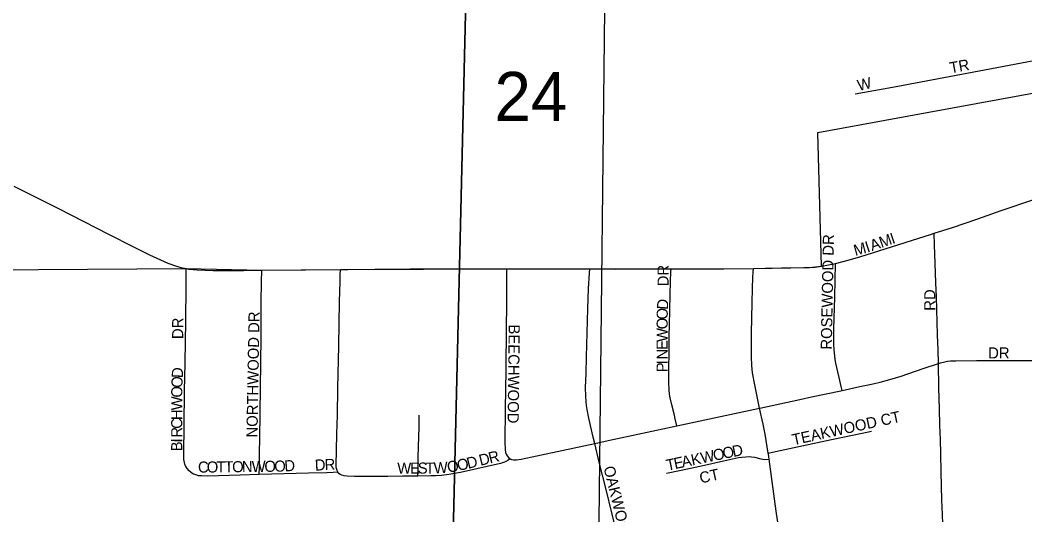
# Model space of a CAD drawing. Extents: x 0 to 34, y 0 to 22.
# Drawn here: x 4.7754 to 5.2041, y 18.5597 to 18.7709 of the extents above; entities that cross this region are included whole.
import ezdxf

# ---------------------------------------------------------------- set-up
doc = ezdxf.new("R2010")
doc.units = 0
for name, color, linetype in [('GM_X_City_Street', 7, 'Continuous'), ('GM_X_City_Street_Text', 7, 'Continuous'), ('GM_X_Corporation', 7, 'Continuous'), ('GM_X_County_Road', 7, 'Continuous'), ('GM_X_Section', 7, 'Continuous'), ('GM_X_Section_Text', 7, 'Continuous')]:
    doc.layers.add(name, color=color, linetype=linetype)

msp = doc.modelspace()

# ---------------------------------------------------------------- linework, layer by layer
at = {"layer": 'GM_X_City_Street'}
for points in [[(5.13165, 18.73941), (5.14761, 18.74238), (5.162, 18.74505), (5.1868, 18.74968), (5.20785, 18.75366), (5.22221, 18.75626), (5.22954, 18.75761), (5.2375, 18.75916), (5.2537, 18.76214), (5.28766, 18.76837)], [(5.16537, 18.67995), (5.17314, 18.68248), (5.18403, 18.68616), (5.19401, 18.68965), (5.2074, 18.69418)], [(5.12335, 18.66709), (5.12598, 18.66772), (5.12871, 18.66843), (5.13406, 18.66997), (5.14176, 18.67241), (5.16428, 18.67959), (5.16537, 18.67995)], [(5.16723, 18.62437), (5.16705, 18.63018), (5.16685, 18.63662), (5.16633, 18.65278), (5.16612, 18.65875), (5.16567, 18.67113), (5.16554, 18.67485), (5.16537, 18.67995)], [(4.84831, 18.57794), (4.84753, 18.5786), (4.84667, 18.5796), (4.84599, 18.58074), (4.84571, 18.58134), (4.84551, 18.58207), (4.84529, 18.58339), (4.84522, 18.58586), (4.84539, 18.59794), (4.84562, 18.61255), (4.84579, 18.62468), (4.84607, 18.64242), (4.84631, 18.65731), (4.84625, 18.66485)], [(4.87744, 18.57712), (4.87749, 18.57996), (4.8776, 18.58628), (4.8777, 18.59253), (4.87827, 18.63547), (4.87831, 18.64293), (4.87834, 18.65073), (4.87847, 18.6591), (4.87854, 18.66417)], [(4.91092, 18.57814), (4.91066, 18.57863), (4.9105, 18.57908), (4.91038, 18.57961), (4.91033, 18.58027), (4.91027, 18.58093), (4.91042, 18.58737), (4.9106, 18.5944), (4.91077, 18.60238), (4.91097, 18.61386), (4.9114, 18.63187), (4.91175, 18.65081), (4.91197, 18.65926), (4.91204, 18.6621), (4.91211, 18.66452)], [(4.98299, 18.66481), (4.98296, 18.6615), (4.98293, 18.65871), (4.98292, 18.65561), (4.98289, 18.64874), (4.98278, 18.64029), (4.98266, 18.62143), (4.98241, 18.60496), (4.98224, 18.59078), (4.98236, 18.58761), (4.98254, 18.58645), (4.9828, 18.58563), (4.98319, 18.58489), (4.98372, 18.58426), (4.98438, 18.58376), (4.98446, 18.58372)], [(5.02056, 18.59025), (5.01991, 18.5929), (5.01801, 18.6011), (5.0173, 18.60478), (5.01708, 18.60641), (5.01689, 18.6082), (5.01674, 18.61039), (5.01669, 18.61413), (5.01685, 18.62005), (5.01708, 18.62719), (5.0176, 18.6477), (5.01796, 18.65638), (5.01838, 18.66298), (5.01849, 18.66479)], [(5.05562, 18.59777), (5.05478, 18.60132), (5.05471, 18.60162), (5.05441, 18.60282), (5.05341, 18.60672), (5.05274, 18.60974), (5.05249, 18.61134), (5.0523, 18.6131), (5.05217, 18.61622), (5.05215, 18.62056), (5.0523, 18.6308), (5.05235, 18.63297), (5.05239, 18.63637), (5.05249, 18.6407), (5.05265, 18.64721), (5.0528, 18.65372), (5.05296, 18.65939), (5.05308, 18.66352), (5.05311, 18.66473)], [(5.0909, 18.60533), (5.09074, 18.60605), (5.08886, 18.61519), (5.08792, 18.62042), (5.08759, 18.62353), (5.08743, 18.62728), (5.08749, 18.63712), (5.08775, 18.65046), (5.08791, 18.65636), (5.08808, 18.66105), (5.08815, 18.66337), (5.08824, 18.66498)], [(5.11729, 18.66588), (5.12335, 18.66709)], [(5.12613, 18.6129), (5.12574, 18.61451), (5.12483, 18.61835), (5.12428, 18.62082), (5.12386, 18.62266), (5.12345, 18.62449), (5.12315, 18.62612), (5.12294, 18.62762), (5.12273, 18.63013), (5.12263, 18.63269), (5.12257, 18.63406), (5.12256, 18.63519), (5.12256, 18.63673), (5.12256, 18.63903), (5.12295, 18.65288), (5.12335, 18.66709)], [(5.16723, 18.62437), (5.16813, 18.62466), (5.16996, 18.62512), (5.17101, 18.6253), (5.17235, 18.62547), (5.17468, 18.62553), (5.18339, 18.62562), (5.1893, 18.62563), (5.20422, 18.6257), (5.2064, 18.6257), (5.20903, 18.6257)], [(5.12613, 18.6129), (5.13372, 18.61456), (5.13789, 18.61544), (5.13985, 18.61582), (5.14235, 18.61642), (5.14643, 18.61752), (5.1513, 18.61903), (5.16071, 18.62226), (5.16723, 18.62437)], [(5.17032, 18.51676), (5.17012, 18.5235), (5.16974, 18.53396), (5.16949, 18.54102), (5.16928, 18.54791), (5.16916, 18.55217), (5.16903, 18.55593), (5.1689, 18.55985), (5.16869, 18.56624), (5.1684, 18.57794), (5.16821, 18.58601), (5.16802, 18.59185), (5.16785, 18.59811), (5.16764, 18.60508), (5.16741, 18.61392), (5.16723, 18.62437)], [(5.0909, 18.60533), (5.09099, 18.60535), (5.108, 18.60899), (5.1131, 18.61014), (5.12553, 18.61277), (5.12613, 18.6129)], [(5.05562, 18.59777), (5.06548, 18.59988), (5.0909, 18.60533)], [(5.09459, 18.58607), (5.09328, 18.59422), (5.09241, 18.59847), (5.0909, 18.60533)], [(4.94511, 18.57633), (4.94518, 18.57954), (4.9453, 18.58431), (4.94541, 18.58888), (4.94563, 18.59721), (4.9457, 18.60226)], [(5.02056, 18.59025), (5.02627, 18.59147), (5.05562, 18.59777)], [(5.09459, 18.58607), (5.09772, 18.58675), (5.12162, 18.59194), (5.13465, 18.59468), (5.13859, 18.59551)], [(4.98446, 18.58372), (4.98513, 18.58341), (4.98594, 18.58325), (4.9865, 18.58322), (4.9872, 18.58324), (4.9892, 18.58357), (4.99588, 18.58495), (5.00652, 18.58724), (5.02056, 18.59025)], [(5.04262, 18.48878), (5.04262, 18.49163), (5.04252, 18.49314), (5.04243, 18.49417), (5.04228, 18.4955), (5.04198, 18.49721), (5.0417, 18.49875), (5.03853, 18.51334), (5.03488, 18.53037), (5.03064, 18.54909), (5.02805, 18.56012), (5.02527, 18.57115), (5.02249, 18.58229), (5.02056, 18.59025)], [(4.98446, 18.58372), (4.98344, 18.58301), (4.98288, 18.58262), (4.98212, 18.5822), (4.98038, 18.58163), (4.96333, 18.57791), (4.95832, 18.577), (4.95513, 18.57662), (4.95279, 18.57649), (4.95065, 18.57643), (4.94511, 18.57633)], [(5.05125, 18.5775), (5.05743, 18.57883), (5.06734, 18.581), (5.07554, 18.58285), (5.08194, 18.58418), (5.08334, 18.5844), (5.08499, 18.5846), (5.08654, 18.58464), (5.08746, 18.58459), (5.08868, 18.58438), (5.09146, 18.58367), (5.09234, 18.58349), (5.09318, 18.58345), (5.09495, 18.58356)], [(5.09495, 18.58356), (5.09465, 18.58565), (5.09459, 18.58607)], [(5.11195, 18.5042), (5.11172, 18.50534), (5.10984, 18.51441), (5.10852, 18.52015), (5.1071, 18.52578), (5.10548, 18.53167), (5.10236, 18.54288), (5.10113, 18.54682), (5.10012, 18.55031), (5.09985, 18.55121), (5.09953, 18.55241), (5.09925, 18.55365), (5.09891, 18.5553), (5.09853, 18.55744), (5.09797, 18.56133), (5.09627, 18.57397), (5.09495, 18.58356)], [(4.84831, 18.57794), (4.84934, 18.57734), (4.85027, 18.57695), (4.85142, 18.57663), (4.85281, 18.57656), (4.85533, 18.57649), (4.86933, 18.57687), (4.87744, 18.57712)], [(4.87744, 18.57712), (4.88796, 18.57744), (4.89852, 18.57764), (4.90625, 18.5778), (4.90893, 18.57797), (4.91092, 18.57814)], [(4.94511, 18.57633), (4.94474, 18.57632), (4.93853, 18.57628), (4.93232, 18.57618), (4.92363, 18.57616), (4.91802, 18.57609), (4.91489, 18.57623), (4.91361, 18.57639), (4.91262, 18.57665), (4.91201, 18.577), (4.91145, 18.57745), (4.91099, 18.578), (4.91092, 18.57814)]]:
    msp.add_lwpolyline(points, dxfattribs=at)
at = {"layer": 'GM_X_Corporation'}
msp.add_lwpolyline([(4.76193, 18.66434), (4.84625, 18.66485), (4.87854, 18.66417), (4.91211, 18.66451), (4.98299, 18.66481), (5.01849, 18.66479), (5.05311, 18.66473), (5.08824, 18.66498), (5.11224, 18.66538), (5.11729, 18.66588), (5.11576, 18.723), (5.2407, 18.74588)], dxfattribs=at)
at = {"layer": 'GM_X_County_Road'}
for points in [[(4.7728, 18.70004), (4.77765, 18.69765), (4.79188, 18.6905), (4.8131, 18.67953), (4.82375, 18.67414), (4.83066, 18.67069), (4.83839, 18.66716), (4.84215, 18.66585), (4.844, 18.66532), (4.84625, 18.66485)], [(4.84625, 18.66485), (4.84733, 18.66466), (4.84924, 18.66443), (4.85094, 18.66432), (4.85775, 18.66412), (4.8708, 18.66409), (4.87854, 18.66417)], [(4.87854, 18.66417), (4.89722, 18.66437), (4.91211, 18.66452)], [(4.91211, 18.66452), (4.91524, 18.66454), (4.92675, 18.66464), (4.94167, 18.66472), (4.94695, 18.66475), (4.96622, 18.66475), (4.98021, 18.66482), (4.98299, 18.66481)], [(4.98299, 18.66481), (4.99762, 18.66476), (5.01503, 18.66483), (5.01849, 18.66479)], [(5.01849, 18.66479), (5.02933, 18.66468), (5.05311, 18.66473)], [(5.05311, 18.66473), (5.05917, 18.66475), (5.07563, 18.66479), (5.08824, 18.66498)], [(5.08824, 18.66498), (5.09326, 18.66506)], [(5.09326, 18.66506), (5.10019, 18.66517), (5.10982, 18.66529), (5.11224, 18.66538), (5.11462, 18.66555), (5.11729, 18.66588)]]:
    msp.add_lwpolyline(points, dxfattribs=at)
at = {"layer": 'GM_X_Section'}
for points in [[(4.47149, 18.91545), (4.96887, 18.91739), (4.95692, 18.41406), (4.46827, 18.41225)], [(4.96887, 18.91739), (5.22048, 18.91682), (5.36618, 18.91648), (5.36674, 18.86475), (5.0257, 18.8658), (5.02156, 18.49258), (5.46515, 18.49757), (5.46379, 18.41876), (4.95692, 18.41406)]]:
    msp.add_lwpolyline(points, close=True, dxfattribs=at)

# ---------------------------------------------------------------- texts
at = {"layer": 'GM_X_City_Street_Text'}
for s, height, rotation, p in [('TR', 0.004735, 10.495, (5.17242, 18.74817)), ('W', 0.00473, 13.0032, (5.13321, 18.74066)), ('ROSEWOOD DR', 0.0047348, 88.8753, (5.12169, 18.63023)), ('I', 0.00473, 18.3996, (5.13686, 18.67165)), ('A', 0.00473, 18.8761, (5.13888, 18.67232)), ('M', 0.00473, 18.8994, (5.14282, 18.67367)), ('I', 0.00473, 18.8774, (5.14755, 18.67529)), ('M', 0.00473, 14.7519, (5.13171, 18.67028)), ('DR', 0.004735, 90, (5.0521, 18.6573)), ('RD', 0.004735, 90, (5.16586, 18.64688)), ('D', 0.00473, 85.7555, (5.05174, 18.6472)), ('NORTHWOOD DR', 0.0047348, 89.0042, (4.87669, 18.59273)), ('O', 0.00473, 89.2786, (5.05169, 18.64311)), ('DR', 0.004735, 90, (4.84502, 18.6348)), ('O', 0.00473, 89.9781, (5.05169, 18.63896)), ('BEECHWOOD', 0.004735, 269.3562, (4.98388, 18.64104)), ('W', 0.00473, 89.9798, (5.05169, 18.63354)), ('E', 0.00473, 89.9727, (5.05169, 18.63021)), ('N', 0.00473, 89.9781, (5.05169, 18.62605)), ('DR', 0.004735, 0, (5.18841, 18.62652)), ('I', 0.00473, 89.985, (5.05169, 18.62396)), ('D', 0.00473, 87.7041, (4.84482, 18.61808)), ('P', 0.00473, 89.9727, (5.05169, 18.62063)), ('O', 0.00473, 87.8797, (4.84466, 18.61392)), ('O', 0.00473, 89.2349, (4.84461, 18.60978)), ('W', 0.00473, 89.9832, (4.84461, 18.60438)), ('H', 0.00473, 89.9928, (4.84461, 18.60022)), ('TEAKWOOD CT', 0.0047348, 12.4074, (5.10531, 18.58942)), ('C', 0.00473, 89.9757, (4.84461, 18.59647)), ('R', 0.00473, 89.994, (4.84461, 18.59272)), ('I', 0.00473, 89.9563, (4.8446, 18.59063)), ('B', 0.00473, 90, (4.8446, 18.58688)), ('R', 0.00473, 13.7064, (4.97586, 18.58167)), ('K', 0.00473, 11.82, (5.06216, 18.5808)), ('W', 0.00473, 11.8177, (5.06624, 18.58166)), ('O', 0.00473, 11.8278, (5.07154, 18.58277)), ('O', 0.00473, 11.82, (5.07562, 18.58362)), ('D', 0.00473, 10.4612, (5.07967, 18.58447)), ('C', 0.00473, 0.6558, (4.85134, 18.57777)), ('O', 0.00473, 0.6687, (4.85509, 18.57781)), ('T', 0.00473, 0.6557, (4.85926, 18.57786)), ('T', 0.00473, 0.6557, (4.86259, 18.5779)), ('O', 0.00473, 0.6558, (4.86593, 18.57794)), ('N', 0.00473, 0.6687, (4.87009, 18.57799)), ('W', 0.00473, 0.6556, (4.87426, 18.57804)), ('O', 0.00473, 0.6687, (4.87968, 18.5781)), ('O', 0.00473, 1.3338, (4.8839, 18.57815)), ('D', 0.00473, 4.2024, (4.88833, 18.57826)), ('D', 0.00473, 3.0829, (4.90128, 18.5786)), ('R', 0.00473, 2.672, (4.90543, 18.57882)), ('W', 0.00473, 0.1009, (4.93633, 18.57735)), ('E', 0.00473, 0.0954, (4.94175, 18.57736)), ('S', 0.00473, 0.082, (4.94508, 18.57737)), ('T', 0.00473, 0.1089, (4.94841, 18.57737)), ('W', 0.00473, 3.0668, (4.95201, 18.57739)), ('O', 0.00473, 9.4516, (4.958, 18.57774)), ('O', 0.00473, 12.4995, (4.96238, 18.57848)), ('D', 0.00473, 13.6192, (4.96654, 18.5794)), ('D', 0.00473, 13.7023, (4.97181, 18.58068)), ('T', 0.00473, 11.8296, (5.05156, 18.57858)), ('E', 0.00473, 11.8296, (5.05482, 18.57927)), ('A', 0.00473, 11.82, (5.05808, 18.57995)), ('OAKWOOD DR', 0.004735, 283.7473, (5.02428, 18.57999)), ('CT', 0.004735, 12.5327, (5.06582, 18.57313))]:
    msp.add_text(s, height=height, rotation=rotation, dxfattribs=at).set_placement(p)
at = {"layer": 'GM_X_Section_Text'}
msp.add_text('24', height=0.020928, rotation=0, dxfattribs=at).set_placement((4.97779, 18.7279))

doc.saveas('drawing.dxf')
